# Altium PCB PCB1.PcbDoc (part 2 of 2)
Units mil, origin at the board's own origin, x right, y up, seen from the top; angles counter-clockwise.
Board outline 4950 x 3450 mil, 4 copper layers (Top Layer, VCC, GND, Bottom Layer), stack 79.834 mil thick; 154 components, 59 nets, 358 pads, 74 vias.
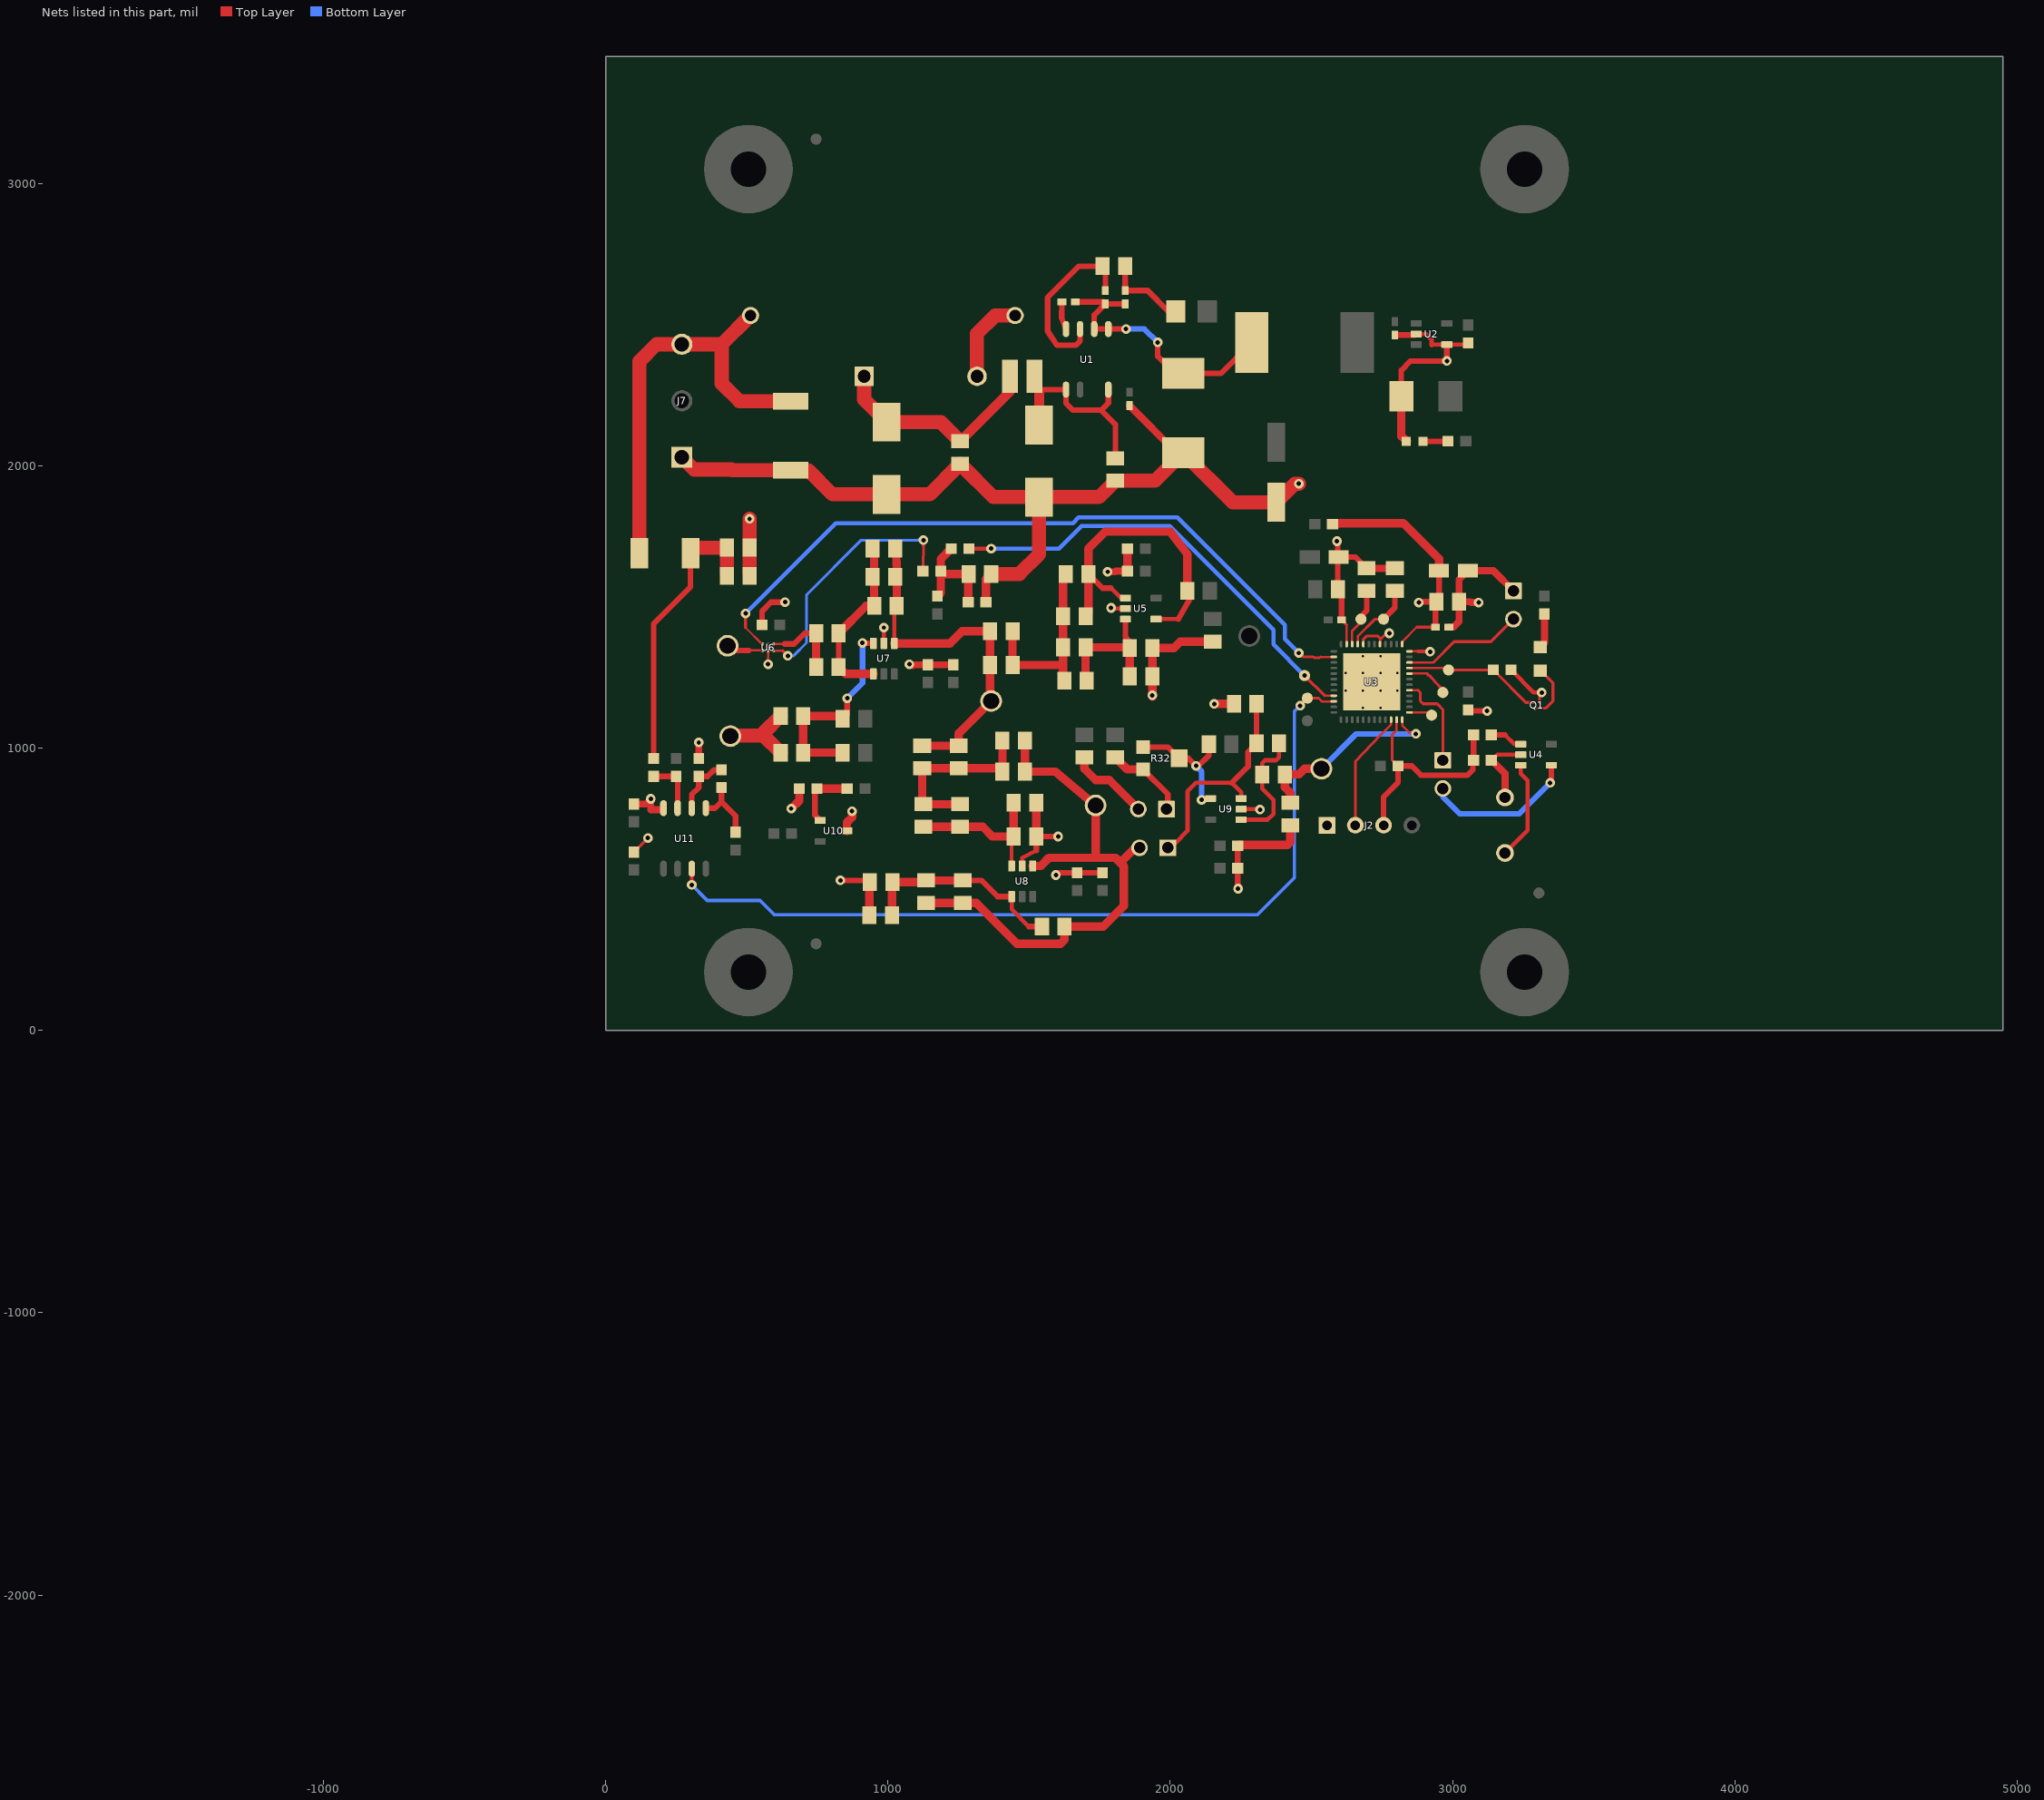
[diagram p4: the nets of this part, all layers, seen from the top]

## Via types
v1: diameter 34, hole 16, Top Layer to Bottom Layer, 62 vias
v2: diameter 19.68, hole 7.87, Top Layer to Bottom Layer, 12 vias

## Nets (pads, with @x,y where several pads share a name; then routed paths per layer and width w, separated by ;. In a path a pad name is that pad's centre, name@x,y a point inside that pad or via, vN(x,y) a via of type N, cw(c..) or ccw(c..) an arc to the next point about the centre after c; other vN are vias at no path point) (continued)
AGND: C2.2 C3.2 C5.2 C6.2 C7.2 C8.2 C9.2 C10.2 C11.2 C12.2 C13.2 C14.2 C15.2 C16.1 C17.1 C18.2 C19.2 C20.2 C21.2 C22.1 C23.1 C24.2 C25.2 C26.1 C31.2 C32.2 C37.2 C38.2 C39.2 C40.2 C41.2 C42.2 C43.2 C44.2 C45.2 D3.2 D4.1 D5.2 D6.2 J2.1 J3.1 J6.1 J7.1 Q1.A2 R4.1 R6.1 R10.1 R24.2 R25.2 R28.1 R29.1 R32.3 R36.1 R38.1 R40.1 R48.1 S1.1 U2.2 U2.4 U3.36 U3.41 U3.44 U3.47 U3.49 U4.2 U5.2 U6.2 U7.2 U8.2 U9.2 U10.3 U11.4 | length 9008.4
  Top Layer w8: 575.59,1316.56 U6.2@575.59,1344.75 ; U3.47@2624.7,1368.12 2624.7,1436.46 ; U3.44@2683.76,1368.12 2683.76,1384.73 ; U3.41@2742.81,1368.12 2742.81,1383.79 ; U3.36@2847.15,1342.53 2876.83,1342.53
  Top Layer w10: C44.2@100,631.5 v1(150,681.5) ; v1(575.59,1296.56) 575.59,1316.56 ; C10.2@2606.91,1454.26 2624.7,1436.46 ; 2683.76,1384.73 2695.59,1396.56 2735.59,1396.56 2745.59,1386.56 2765.59,1406.56 v1(2775.59,1406.56) ; Q1.A2@3308.53,1161.56 3308.53,1183.46 3315.59,1190.52 v1(3315.59,1196.56)
  Top Layer w12: 2877.15,1342.21 2911.55,1342.21 2912.52,1341.25 v1(2920.59,1341.25)
  Top Layer w15: U7.2@985.59,1370.7 985.59,1406.56 ; U8.2@1475.59,582.15 1475.59,610.95 1525.59,636.56 ; v1@1792.6,1493.94 U5.2@1841.46,1493.94 ; U9.2@2251.24,783.63 v1@2315.69,783.63 ; U2.2@2871.46,2466.56 2905.91,2466.56 2925.59,2446.88 2925.59,2426.56 2928.19,2429.16 U2.4@2979.72,2429.16 3049.68,2429.16 C6.2@3055.59,2435.07 ; C41.2@3139.05,956.56 3158.74,976.25 U4.2@3241.46,976.25 ; R6.1@3207.09,1276.56 3287.09,1196.56 v1(3315.59,1196.56)
  Top Layer w20: C26.1@554.09,1436.56 554.09,1485.07 585.59,1516.56 v1(635.59,1516.56) ; v1(831.63,530.97) 905.77,530.97 ; R24.2@928.52,518.04 934.39,523.9 R24.2@935.59,525.1 ; 1525.59,636.56 R28.1@1525.59,686.56 v1(1602.78,686.56) ; v1(1594.67,549.99) 1602.74,558.06 C37.2@1670,558.06 C39.2@1760,558.06 ; v1(1789.98,1496.56) v1@1792.6,1493.94 ; R32.3@1903.8,924.26 1991.18,836.88 1991.18,788.02 J6.1@1986.79,783.63 ; C38.2@2238.92,653.94 C40.2@2238.92,573.94 2238.92,503.1 v1(2240.08,501.94) ; v1@2315.69,783.63 v1(2317.76,781.56) ; v1(2590.59,1732.63) 2593.29,1729.94 C12.2@2593.29,1562.36 2606.91,1548.74 C10.2@2606.91,1454.26 ; C11.2@2596.77,1676.56 2655.59,1676.56 C17.1@2695.59,1636.56 ; C5.2@2795.59,2462.94 2867.83,2462.94 U2.2@2871.46,2466.56 ; D3.2@2818.27,2246.56 2818.27,2337.82 2851.14,2370.7 v1(2979.72,2370.7) U2.4@2979.72,2429.16 ; C21.2@3062.09,1131.56 v1(3122.17,1131.56)
  Top Layer w25: C44.2@100,631.5 C44.2@105.05,636.54 ; C45.2@100,801.5 141.5,801.5 v1(160,820) 160,781.5 199.21,781.5 U11.4@205,787.28 ; R10.1@330,962.8 v1(330,1020) ; v1@1087.36,1292.63 1089.86,1295.12 C31.2@1141.2,1295.12 C32.2@1231.2,1295.12 ; v1(1777.81,1624.18) 1804.63,1624.18 1807.01,1626.56 C24.2@1848.5,1626.56 ; R4.1@1855.59,2212.94 2022.46,2046.07 D6.2@2045.59,2046.07 ; C17.1@2695.59,1636.56 C16.1@2795.59,1636.56 ; C15.2@2986.91,1428.02 3003.29,1428.02 3023.29,1448.02 C13.2@3023.29,1518.02 ; v1(3092.17,1515.32) 3065.98,1515.32 3063.29,1518.02 C13.2@3023.29,1518.02 ; C41.2@3139.05,956.56 3185.59,910.03 S1.1@3185.59,824.99 ; J3.1@3215.59,1556.56 3144.13,1628.02 C14.2@3054.47,1628.02 3023.29,1596.84 C13.2@3023.29,1518.02
  Top Layer w30: v1(657.56,785.43) 685.75,813.61 R38.1@685.75,856.56 ; U10.3@854.49,706.56 854.49,736.64 872.81,754.97 v1(872.81,776.18) ; R25.2@934.39,408.04 R24.2@934.39,523.9 ; R40.1@1347.09,1516.56 1347.09,1598.06 C20.2@1365.59,1616.56 ; R28.1@1525.59,686.56 R29.1@1525.59,806.56 ; C42.2@1805.59,966.56 1847.89,924.26 R32.3@1903.8,924.26 ; C24.2@1848.5,1626.56 C25.2@1848.5,1706.56 ; v1@1936.69,1182.37 C23.1@1936.69,1253.94 C22.1@1936.69,1353.94 2012.97,1353.94 2035.59,1376.56 C18.2@2150,1376.56 ; v1(2155.59,1156.56) R36.1@2225.59,1156.56 ; C38.2@2238.92,653.94 2241.54,656.56 2415.59,656.56 2425.59,666.56 C19.2@2425.59,726.56 ; 2818.27,2104.04 D3.2@2818.27,2246.56 ; 2820.26,2104.04 D5.2@2837.74,2086.56
  Top Layer w50: J7.1@270,2030 313.44,1986.56 445.59,1986.56 447.83,1984.32 D4.1@655.59,1984.32 717.83,1984.32 803.54,1898.61 C7.2@995.59,1898.61 1147.64,1898.61 C8.2@1255.59,2006.56 1373.54,1888.61 C2.2@1535.59,1888.61 ; C43.2@510,1620 510,1720 v1(510,1811.57) ; C20.2@1365.59,1616.56 1465.59,1616.56 1535.59,1686.56 C2.2@1535.59,1888.61 ; v1(2455.59,1936.56) 2441.89,1936.56 C9.2@2375.59,1870.26 2221.4,1870.26 D6.2@2045.59,2046.07 1946.08,1946.56 C3.2@1805.59,1946.56 1747.64,1888.61 C2.2@1535.59,1888.61
  other v1: 1936.69,1186.56 1075.59,1296.56 985.59,1426.56
  other v2: 2681.65,1142.72 2744.92,1142.72 2621.75,1202.62 2681.65,1202.62 2744.92,1202.62 2804.82,1202.62 2621.75,1265.89 2681.65,1265.89 2744.92,1265.89 2804.82,1265.89 2681.65,1325.79 2744.92,1325.79
COMP_OP: C19.1 R42.2 TP9.1 U3.24 | length 713.4
  Top Layer w8: U3.24@2821.55,1100.4 2821.55,1080 2829.05,1072.5 2844.05,1057.5 2851.55,1050 v1(2870,1050)
  Top Layer w30: C19.1@2425.59,806.56 2425.59,840.56 2405.59,860.56 R42.2@2405.59,906.56 2455.59,906.56 2475.59,926.56 TP9.1@2535.59,926.56
  Bottom Layer w20: TP9.1@2535.59,926.56 2655.59,1046.56 2659.03,1050 v1(2870,1050)
DVCC: C13.1 C14.1 C15.1 L3.1 U3.37 | length 890.2
  Top Layer w8: U3.37@2821.55,1368.12 2821.55,1376.29 2873.29,1428.02
  Top Layer w10: 2873.29,1428.02 C15.1@2939.67,1428.02
  Top Layer w20: v1(2880.59,1515.32) 2885.2,1515.32 2887.89,1518.02 C13.1@2943.29,1518.02 ; C15.1@2939.67,1428.02 2939.67,1514.4 C13.1@2943.29,1518.02 ; C14.1@2952.11,1628.02 2952.11,1526.84 C13.1@2943.29,1518.02
  Top Layer w30: L3.1@2574.78,1792.36 2591.39,1792.36 2595.59,1796.56 2825.59,1796.56 2952.11,1670.05 C14.1@2952.11,1628.02
FAULT: J3.2 U3.34 | length 432
  Top Layer w8: U3.34@2847.15,1303.16 2932.18,1303.16
  Top Layer w10: 2932.18,1303.16 3005.59,1376.56 3135.59,1376.56 J3.2@3215.59,1456.56
NetC1_1: C1.1 U1.4 | length 98.7
  Top Layer w20: C1.1@1616.42,2580.03 1615.59,2522.55 U1.4@1630.59,2484.16
NetC1_2: C1.2 C4.2 D6.1 L2.1 R2.1 U1.1 U1.2 | length 981.9
  Top Layer w20: C1.2@1663.66,2580.03 1762.95,2580.03 R2.1@1770.04,2572.94 ; C4.2@1840.04,2572.94 R2.1@1770.04,2572.94 ; v1(1843.19,2484.16) U1.1@1780.59,2484.16 U1.2@1730.59,2484.16 1730.59,2533.49 R2.1@1770.04,2572.94 ; v1(1955.59,2436.56) 1955.59,2387.05 2015.59,2327.05 D6.1@2045.59,2327.05 2179.07,2327.05 L2.1@2288.58,2436.56
  Bottom Layer w20: v1(1843.19,2484.16) 1907.99,2484.16 v1(1955.59,2436.56)
NetC2_1: C2.1 C3.1 L1.2 U1.5 U1.8 | length 701.2
  Top Layer w20: L1.2@1518.9,2283.25 1532.56,2269.59 U1.5@1630.59,2269.59 1630.59,2221.56 1655.59,2196.56 1755.59,2196.56 ; U1.8@1780.59,2269.59 1780.59,2221.56 1755.59,2196.56 ; C3.1@1805.59,2026.56 1805.59,2146.56 1755.59,2196.56
  Top Layer w35: L1.2@1532.56,2269.59 1535.59,2266.56 C2.1@1535.59,2144.51
NetC4_1: C4.1 D2.1 R1.2 | length 296.3
  Top Layer w20: R1.2@1840.04,2706.56 C4.1@1840.04,2620.18 1919.88,2620.18 1993.5,2546.56 D2.1@2019.49,2546.56
NetC7_1: C7.1 C8.1 D1.1 L1.1 | length 786.5
  Top Layer w35: C8.1@1255.59,2086.56 1432.28,2263.25 L1.1@1432.28,2316.56
  Top Layer w50: D1.1@915.59,2316.56 915.59,2234.51 C7.1@995.59,2154.51 1187.64,2154.51 C8.1@1255.59,2086.56
NetC16_2: C16.2 TP14.1 U3.45 | length 260.5
  Top Layer w8: U3.45@2664.07,1368.12 2664.07,1395.05
  Top Layer w10: 2664.07,1395.05 2725.59,1456.56 TP14.1@2755.59,1456.56
  Top Layer w20: TP14.1@2755.59,1456.56 2795.59,1496.56 C16.2@2795.59,1556.56
NetC17_2: C17.2 TP15.1 U3.46 | length 209.7
  Top Layer w8: U3.46@2644.39,1368.12 2644.39,1415.36
  Top Layer w10: 2644.39,1415.36 2675.59,1446.56 TP15.1@2675.59,1456.56
  Top Layer w20: TP15.1@2675.59,1456.56 2675.59,1466.56 2695.59,1486.56 C17.2@2695.59,1556.56
NetC20_1: C20.1 R8.2 R9.1 R39.2 R40.2 | length 391.9
  Top Layer w30: R39.2@1175.59,1538.06 1187.09,1549.55 R9.1@1187.09,1626.56 ; R8.2@1224.09,1706.56 1187.09,1669.55 R9.1@1187.09,1626.56 ; R40.2@1284.09,1516.56 1284.09,1615.07 C20.1@1285.59,1616.56 1197.09,1616.56 R9.1@1187.09,1626.56
NetC22_2: C22.2 C23.2 R13.2 R16.2 U5.3 | length 485.9
  Top Layer w20: R16.2@1700,1243.57 R16.2@1704.39,1239.18 ; U5.3@1841.46,1456.54 1841.46,1392.18 1856.69,1376.94 C22.2@1856.69,1353.94 C22.2@1854.07,1356.56
  Top Layer w30: R16.2@1700,1243.57 R13.2@1700,1356.56 C22.2@1854.07,1356.56 ; C23.2@1856.69,1253.94 C22.2@1856.69,1353.94
NetC27_1: C27.1 R14.1 R17.1 R18.2 R19.2 U7.4 | length 621.3
  Top Layer w20: R19.2@825.59,1286.56 R18.2@825.59,1406.56
  Top Layer w30: R19.2@825.59,1286.56 849.72,1262.43 U7.4@948.19,1262.43 ; R18.2@825.59,1406.56 922.66,1503.63 C27.1@951.2,1503.63 951.2,1623.63 R14.1@951.14,1706.56
NetC27_2: C27.2 C33.2 C36.2 R12.1 R14.2 R15.1 R17.2 TP6.1 U7.1 | length 1260.7
  Top Layer w15: U7.1@1022.99,1370.7 C27.2@1022.99,1495.42
  Top Layer w20: C27.2@1022.99,1495.42 C27.2@1031.2,1503.63
  Top Layer w30: U7.1@1022.99,1370.7 1219.72,1370.7 1262.66,1413.63 R12.1@1361.2,1413.63 R15.1@1361.2,1313.31 ; R14.2@1028.88,1706.56 1031.2,1623.63 C27.2@1031.2,1503.63 ; C33.2@1121.2,1008.02 C36.2@1251.2,1008.02 1251.2,1052.17 TP6.1@1365.59,1166.56 1361.2,1170.95 R15.1@1361.2,1293.94
NetC28_1: C28.1 C29.1 R41.1 U5.1 U5.4 | length 1151.5
  Top Layer w15: 1790,1566.56 1825.22,1531.34 U5.1@1841.46,1531.34 ; U5.4@1949.72,1456.54 2028.69,1456.54
  Top Layer w20: C28.1@1700,1466.56 C28.1@1710,1476.56 ; C29.1@1710,1616.56 1760,1566.56 1790,1566.56 ; 2028.69,1456.54 2069.98,1529.76 R41.1@2069.98,1558.37
  Top Layer w30: C28.1@1710,1476.56 C29.1@1710,1616.56 ; C29.1@1710,1616.56 1709.98,1706.54 1770,1766.56 2000,1766.56 2059.98,1686.59 2059.98,1646.56 2059.98,1566.56 R41.1@2049.98,1556.56
NetC28_2: C28.2 C29.2 R12.2 R13.1 R15.2 R16.1 | length 684.4
  Top Layer w20: R16.1@1620,1243.57 R16.1@1624.39,1239.18 ; C29.2@1620,1606.56 C29.2@1630,1616.56
  Top Layer w30: R12.2@1441.2,1413.63 R15.2@1441.2,1293.94 1613.88,1293.94 1620,1300.07 ; R16.1@1620,1243.57 1620,1300.07 ; C29.2@1620,1606.56 C28.2@1620,1466.56 R13.1@1620,1356.56 1620,1300.07
NetC30_1: C30.1 R24.1 R25.1 R26.1 R27.1 U8.4 | length 744.2
  Top Layer w15: U8.4@1438.19,473.88 1438.19,428.35 1498.52,368.02
  Top Layer w20: R24.1@1014.39,523.9 R24.1@1015.59,525.1 ; R26.1@1129.7,525.1 R26.1@1135.59,530.99 ; R27.1@1265.59,530.99 1331.16,530.99 1388.27,473.88 U8.4@1438.19,473.88 ; 1498.52,368.02 C30.1@1545.59,368.02
  Top Layer w30: R25.1@1014.39,408.04 R24.1@1014.39,523.9 ; R24.1@1015.59,525.1 R26.1@1129.7,525.1 ; R26.1@1135.59,530.99 R27.1@1265.59,530.99
NetC30_2: C30.2 J5.2 R26.2 R27.2 R31.2 R35.2 TP8.1 U8.1 | length 2009.6
  Top Layer w30: R26.2@1135.59,450.99 R27.2@1265.59,450.99 1312.93,450.99 1457.36,306.56 1611.2,306.56 1625.59,320.95 C30.2@1625.59,368.02 1762.66,368.02 1835.59,440.95 1835.59,580.95 1822.79,593.76 ; R31.2@1485.59,1026.56 R35.2@1485.59,916.56 1592.66,916.56 TP8.1@1735.59,796.56 1735.59,610.95 ; U8.1@1512.99,582.15 1541.18,582.15 1569.98,610.95 1735.59,610.95 ; J5.2@1891.18,646.56 1875.59,646.56 1822.79,593.76 ; 1735.59,610.95 1805.59,610.95 1822.79,593.76
NetC33_1: C33.1 C34.2 C35.2 C36.1 R31.1 R35.1 | length 658
  Top Layer w30: C35.2@1255.59,800.95 C34.2@1125.59,800.95 1121.2,805.34 C33.1@1121.2,928.02 C36.1@1251.2,928.02 1394.13,928.02 R35.1@1405.59,916.56 R31.1@1405.59,1026.56
NetC34_1: C34.1 C35.1 R28.2 R29.2 U8.3 | length 561.7
  Top Layer w12: U8.3@1438.19,582.15 R28.2@1438.19,679.16
  Top Layer w20: R28.2@1438.19,679.16 R28.2@1445.59,686.56
  Top Layer w30: C34.1@1125.59,720.95 C35.1@1255.59,720.95 1335.59,720.95 1369.98,686.56 R28.2@1445.59,686.56 R29.2@1445.59,806.56
NetC43_1: C43.1 R45.1 R46.1 R48.2 | length 970.7
  Top Layer w20: R46.1@170,962.8 170,1440 300.55,1570.55 R45.1@300.55,1690
  Top Layer w50: R45.1@330,1710 429.45,1710 C43.1@430,1620
NetD1_2: D1.2 RF1.1 | length 312.8
  Top Layer w50: D1.2@1315.59,2316.56 1315.59,2468.06 1379.71,2532.18 RF1.1@1450.37,2532.18
NetD5_1: D5.1 R3.1 | length 89
  Top Layer w20: D5.1@2894.8,2086.56 R3.1@2983.78,2086.56
NetD8_1: D8.1 Q1.B1 Q1.B2 | length 203.5
  Top Layer w10: Q1.B1@3288.85,1141.88 Q1.B2@3308.53,1141.88 3330.91,1141.88 3355.59,1166.56 3355.59,1229.99 D8.1@3310.99,1274.59
NetD8_2: D8.2 R5.2 | length 123.8
  Top Layer w25: D8.2@3310.99,1357.26 3325.59,1371.86 R5.2@3325.59,1475.07
NetJ4_2: J4.2 U4.4 | length 514.4
  Top Layer w20: v1(3345.59,876.56) 3349.72,880.7 U4.4@3349.72,938.84
  Bottom Layer w20: 2965.59,826.56 3025.59,766.56 3235.59,766.56 v1(3345.59,876.56)
NetJ5_1: J5.1 R34.1 R36.2 U9.3 | length 786.9
  Top Layer w15: J5.1@1986.79,663.63 2018.25,663.63 2061.18,706.56 2061.18,846.56 2091.18,876.56 2217.67,876.56 2251.24,842.99 U9.3@2251.24,821.03
  Top Layer w20: 2217.67,876.56 2275.59,934.48 2275.59,986.56 R34.1@2305.59,1016.56 R36.2@2305.59,1156.56
NetJ6_2: J6.2 R43.2 | length 290.4
  Top Layer w30: R43.2@1695.59,966.56 1695.59,926.56 1735.59,886.56 1783.86,886.56 J6.2@1886.79,783.63
NetQ1_A1: Q1.A1 R6.2 TP3.1 U3.33 | length 492.2
  Top Layer w8: U3.33@2847.15,1283.47 TP3.1@2978.68,1283.47
  Top Layer w10: TP3.1@2978.68,1283.47 TP3.1@2985.59,1276.56 R6.2@3144.09,1276.56 3259.09,1161.56 Q1.A1@3288.85,1161.56
NetR1_1: R1.1 R2.2 U1.3 | length 640.5
  Top Layer w20: U1.3@1680.59,2484.16 1680.59,2441.56 1665.59,2426.56 1598.92,2426.56 1565.59,2476.56 1565.59,2595.58 1676.57,2706.56 R1.1@1760.04,2706.56 1770.04,2696.56 R2.2@1770.04,2620.18
NetR10_2: R10.2 R44.1 U11.2 | length 212.4
  Top Layer w20: U11.2@305,787.28 305,835 330,860 R10.2@330,899.8 361.26,899.8 384.25,922.8 R44.1@410,922.8
NetR11_1: R11.1 U4.1 | length 118
  Top Layer w15: 3185.59,1046.56 3218.5,1013.65 U4.1@3241.46,1013.65
  Top Layer w20: R11.1@3137.09,1046.56 3185.59,1046.56
NetR18_1: R18.1 R19.1 U6.4 | length 286.1
  Top Layer w8: U6.4@595.28,1368.37 633.78,1368.37
  Top Layer w20: 633.78,1368.37 667.4,1368.37 705.59,1406.56 R18.1@745.59,1406.56
  Top Layer w30: R19.1@745.59,1286.56 R18.1@745.59,1406.56
NetR20_1: R20.1 R21.1 TP7.1 | length 295.3
  Top Layer w50: TP7.1@445.59,1046.56 448.52,1043.63 560,1043.63 ; R21.1@620,983.63 560,1043.63 ; R20.1@620,1113.63 560,1053.63 560,1043.63
NetR20_2: R20.2 R21.2 R22.1 R23.1 U7.3 | length 752
  Top Layer w20: R22.1@830,1113.63 R22.1@840,1103.63 845.59,1109.22 855.59,1119.22 v1(855.59,1176.56) ; v1(909.72,1372.43) 909.72,1370.7 U7.3@948.19,1370.7
  Top Layer w30: R22.1@830,1113.63 R20.2@700,1113.63 R21.2@700,983.63 R23.1@840,983.63
  Bottom Layer w20: v1(855.59,1176.56) 909.72,1230.7 v1(909.72,1372.43)
NetR30_1: R30.1 R32.1 R32.2 U9.4 | length 477.8
  Top Layer w20: R32.1@1903.8,1003 1992.38,1003 R32.2@2031.75,963.63 2064.11,963.63 v1(2091.18,936.56) 2099.73,936.56 2136.79,973.63 R30.1@2136.79,1013.63 ; v1(2111.18,816.56) 2115.65,821.03 U9.4@2142.97,821.03
  Bottom Layer w20: v1(2091.18,936.56) 2111.18,916.56 v1(2111.18,816.56)
NetR34_2: R34.2 R42.1 U9.1 | length 437.6
  Top Layer w15: U9.1@2251.24,746.23 2345.26,746.23 2365.59,766.56 2365.59,816.56 2325.59,856.56 R42.1@2325.59,906.56 2325.59,946.56 2335.59,956.56 2375.59,956.56 2385.59,966.56 R34.2@2385.59,1016.56
NetR37_1: R37.1 R38.2 U10.1 | length 230.2
  Top Layer w20: R38.2@748.74,856.56 741.63,849.45 741.63,762.33 U10.1@760,743.96
  Top Layer w30: R38.2@748.74,856.56 R37.1@855.75,856.56
NetR44_2: R44.2 R47.1 U11.1 | length 243.4
  Top Layer w20: U11.1@355,787.28 387.28,787.28 410,810 ; R44.2@410,859.8 410,810 ; R47.1@460,701.5 460,760 410,810
NetR46_2: R46.2 R49.2 U11.3 | length 194.6
  Top Layer w20: R46.2@170,899.8 R49.2@250,899.8 255,894.8 U11.3@255,787.28
NetS1_2: S1.2 U4.3 | length 353.8
  Top Layer w15: S1.2@3185.59,628.14 3265.59,708.14 3265.59,885.38 3241.46,909.51 U4.3@3241.46,938.84
NetTP5_1: TP5.1 U6.1 | length 122.1
  Top Layer w8: 506.42,1345.73 U6.1@555.91,1345.73
  Top Layer w20: TP5.1@441.2,1363.63 459.09,1345.73 506.42,1345.73
NetTP10_1: TP10.1 U3.25 | length 82.4
  Top Layer w8: U3.25@2847.15,1125.99 2916.16,1125.99 TP10.1@2925.59,1116.56
NetTP13_1: TP13.1 U3.32 | length 153.5
  Top Layer w8: U3.32@2847.15,1263.79 2908.37,1263.79
  Top Layer w10: 2908.37,1263.79 2915.72,1256.44 2917.96,1256.44 2935.46,1238.94 2935.46,1236.69 2965.59,1206.56 TP13.1@2965.59,1196.56
PWM_TEST: R8.1 TP17.1 U3.9 | length 1605.1
  Top Layer w8: 2547.11,1185.05 U3.9@2579.43,1185.05
  Top Layer w10: v1(2475.59,1256.56) 2547.11,1185.05
  Top Layer w15: R8.1@1287.09,1706.56 v1(1365.59,1706.56)
  Bottom Layer w15: v1(1365.59,1706.56) 1605.59,1706.56 1685.59,1786.56 1997.52,1786.56 2365.59,1418.49 2365.59,1366.56 v1(2475.59,1256.56)
RESET: C41.1 J2.3 R7.1 R11.2 U3.23 | length 821.6
  Top Layer w8: 2801.87,1062.84 U3.23@2801.87,1100.4
  Top Layer w10: 2801.87,1062.84 2785.59,1046.56 2785.59,958.06 R7.1@2807.09,936.56
  Top Layer w20: J2.3@2755.59,726.56 2755.59,826.56 2807.09,878.06 R7.1@2807.09,936.56 2855.59,936.56 2888.19,903.96 3052.99,903.96 3072.13,923.1 3072.13,956.56 3074.09,958.53 R11.2@3074.09,1046.56
TEST: R9.2 U6.3 | length 959
  Top Layer w8: U6.3@595.28,1344.75 627.4,1344.75
  Top Layer w10: 627.4,1344.75 v1(645.59,1326.56) ; R9.2@1124.09,1626.56 v1(1125.59,1736.56) 1125.59,1716.56 1124.09,1715.07
  Bottom Layer w10: v1(645.59,1326.56) 665.59,1326.56 711.59,1372.56 711.59,1542.56 905.22,1736.19 v1(1125.59,1736.56) 1106.34,1736.56 1105.96,1736.19
TEST/SBWTCK: J2.2 U3.22 | length 424.9
  Top Layer w8: 2745.59,1046.56 2782.18,1083.16 U3.22@2782.18,1100.4
  Top Layer w10: J2.2@2655.59,726.56 2655.59,951.76 2745.59,1046.56
TEST_EN: U3.2 U6.6 | length 2595.5
  Top Layer w8: 495.59,1426.56 553.78,1368.37 U6.6@555.91,1368.37 ; 2532.29,1322.84 U3.2@2579.43,1322.84
  Top Layer w10: v1(2455.59,1336.56) 2469.31,1322.84 2506.96,1322.84 2510.15,1319.65 2529.1,1319.65 2532.29,1322.84
  Top Layer w12: 495.59,1426.56 v1(495.59,1476.56)
  Bottom Layer w15: v1(495.59,1476.56) 815.59,1796.56 1655.59,1796.56 1675.59,1816.56 2025.59,1816.56 2405.59,1436.56 2405.59,1386.56 v1(2455.59,1336.56)
VAC_IN: D4.2 J7.3 R45.2 RF1.2 | length 1550
  Top Layer w50: R45.2@119.45,1690 119.45,2369.45 180,2430 J7.3@270,2430 411.18,2430 ; RF1.2@513.36,2532.18 411.18,2430 ; D4.2@655.59,2228.81 473.35,2228.81 411.18,2290.97 411.18,2430
VIN_ZC: TP11.1 U3.10 U11.7 | length 3030.5
  Top Layer w8: 2536.79,1165.36 U3.10@2579.43,1165.36
  Top Layer w10: TP11.1@2485.59,1176.56 2525.59,1176.56 2536.79,1165.36
  Top Layer w12: v1(305,515) 305,545 U11.7@310,550 ; v1(2460,1150) 2460,1150.97 TP11.1@2485.59,1176.56
  Bottom Layer w12: v1@300,520 360,460 546.76,460 596.88,409.87 2309.87,409.87 2440,540 2440,1130 v1(2460,1150)
WDI: J4.1 U3.29 | length 344.3
  Top Layer w8: U3.29@2847.15,1204.73 2877.42,1204.73
  Top Layer w10: 2877.42,1204.73 2885.59,1196.56 2885.59,1166.56 2895.59,1156.56 2945.59,1156.56 2965.59,1136.56 J4.1@2965.59,956.56
pads on no net: FID1.1 FID2.1 FID3.1 H1.1 H2.1 H3.1 H4.1 J7.2 U1.6 U3.4 U3.5 U3.6 U3.7 U3.8 U3.12 U3.13 U3.14 U3.15 U3.16 U3.17 U3.18 U3.19 U3.20 U3.21 U3.26 U3.27 U3.28 U3.30 U3.31 U3.35 U3.38 U3.39 U3.40 U3.42 U3.43

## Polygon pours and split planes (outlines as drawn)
AGND on GND "GND-No Net" (solid, pour order 18): 375.59,347.37 90,347.37 90,2046.56 375.59,2046.56 765.59,2046.56 855.59,1956.56 1675.59,1956.56 2205.59,1956.56 2425.59,1956.56 2495.59,1956.56 2605.59,2066.56 2723.62,2184.59 2723.62,2188.53 2723.62,2704.59 2725.59,2706.56 2725.59,2816.56 3445.59,2816.56 3455.59,2806.56 3455.59,346.56 376.73,346.56 376.16,347.13
+3.3V on VCC "VCC-No Net" (solid, pour order 20): 505.59,426.56 3415.59,426.56 3415.59,1866.56 3165.59,2116.56 3155.59,2116.56 3155.59,2606.56 2795.59,2606.56 2795.59,2186.56 2345.59,1736.56 2375.59,1766.56 515.59,1766.56 505.59,1756.56 140,1766.56 140,426.56

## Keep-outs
Keep-Out Layer:
  lines w7: -1240,-2530 -1240,-530 ; -1240,-2530 760,-2530 ; -1240,-2530 -1240,-530 ; -1240,-2530 760,-2530 ; -1240,-530 760,-530 ; -1240,-530 760,-530 ; 760,-2530 760,-530 ; 760,-2530 760,-530
  lines w10: 0,0 3520,0 ; -1875,-1675 -1875,1675 -1875,-1675
  text ".Layer_Name" at 577,-858.49 h60

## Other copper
Top Layer:
  text ".Layer_Name" at 577,-858.49 h60
Bottom Layer:
  text ".Layer_Name" at 577,-858.49 h60

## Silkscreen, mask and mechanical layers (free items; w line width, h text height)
Top Overlay:
  region: 2345.59,316.56 2045.59,316.56 2045.59,216.56 2345.59,216.56
  lines w10: 40,1780 40,2840 50,2870 2650,2870 2760,2760 2760,2120 2410,1770 1820,1770 640,1770 50,1770 40,1780
  text "HV: Do not touch" at 1150,2810 h40
  text "85-265Vac" at 120,2710 h60
  text "TP1" at 210,2560 h60
  text "3.3V" at 2745.59,1966.56 h60
  text "TP2" at 220,1800 h60
  text "155mV" at 70,1190 h60
  text "FAULT" at 3435.59,1146.56 h60 r90
  text "TIDA-00929-E1" at 1745.59,106.56 h108.27
  text ".Layer_Name" at 577,-858.49 h60
Bottom Overlay:
  text ".Layer_Name" at 577,-858.49 h60
Top Paste:
  text ".Layer_Name" at 577,-858.49 h60
Bottom Paste:
  text ".Layer_Name" at 577,-858.49 h60
Top Solder:
  text ".Layer_Name" at 577,-858.49 h60
  text ".Layer_Name" at 577,-858.49 h60
Bottom Solder:
  text ".Layer_Name" at 577,-858.49 h60
Drill Guide:
  text ".Layer_Name" at 577,-858.49 h60
M1 Board Outline:
  lines w10: 0,0 3520,0 3520,3400 0,3400 0,0
  text ".Layer_Name" at 577,-858.49 h60
M2 Board Dimensions:
  rectangle: 125,-400 500,-275
  rectangle: 0,-275 125,-150
  lines w7: 0,-275 1000,-275 ; 125,-400 125,-150 ; 250,-400 250,-150 ; 500,-400 500,-150 ; 750,-400 750,-150 ; 0,-400 0,-150 1000,-150 1000,-400 0,-400
  text ".Layer_Name" at 577,-858.49 h60
M3 3D STEP Top:
  text ".Layer_Name" at 577,-858.49 h60
M4 3D STEP Bottom:
  text ".Layer_Name" at 577,-858.49 h60
M5 Assembly Top:
  lines w10: -292,-930.17 6308,-930.17 ; -292,-726.83 6310,-726.83 ; -292,-523.5 -292,-1133.5 3713,-1133.5 6310,-1133.5 6310,-523.5 -291.5,-523.5 -291.5,-1133.5 1284,-1133.5 ; 2173,-1133.5 2173,-523.5 ; 3440,-726.83 3440,-523.5 ; 4280,-726.83 4280,-523.5 ; 4902,-1140 4902,-937.17
  text "COMPONENTS MARKED 'DNP' SHOULD NOT BE POPULATED." at 1153.5,-318.5 h60
  text "ASSEMBLY VARIANT:" at 1153,-434 h60
  text ".VariantName" at 2189,-434 h60
  text "PCB VIEWED FROM TOP SIDE" at -228.5,-655.67 h60
  text "BOARD #:" at 2248,-655.67 h60
  text ".PRJ_Number" at 2793.5,-655.67 h60
  text "REV:" at 3638,-655.67 h60
  text ".PCB_Rev" at 3929.5,-655.67 h60
  text "SVN REV:" at 4476,-655.67 h60
  text ".VersionControl_RevNumber" at 4982,-655.67 h60
  text "TID #:" at 2248,-859 h60
  text ".TID" at 2793.5,-859 h60
  text "PLOT NAME =" at -228.5,-1064.34 h60
  text ".plot_File_Name" at 577,-1064.34 h60
  text "GENERATED    :" at 2250,-1064.34 h60
  text ".Print_Date" at 3119.5,-1064.34 h60
  text ".Print_Time" at 3848.5,-1064.34 h60
  text "TEXAS INSTRUMENTS" at 5113,-1064.34 h60
M6 Assembly Bottom:
  lines w10: -292.5,-727.33 6309.5,-727.33 ; -290.5,-930.67 6309.5,-930.67 ; 1115.5,-1140.5 1115.5,-937.67 ; 1737.5,-727.33 1737.5,-524 ; 2577.5,-727.33 2577.5,-524 ; 3844.5,-1134 3844.5,-524 ; 4733.5,-1134 6309,-1134 6309,-524 -292.5,-524 -292.5,-1134 2304.5,-1134 6309.5,-1134 6309.5,-524
  text "COMPONENTS MARKED 'DNP' SHOULD NOT BE POPULATED." at 6102,-318 h60
  text ".VariantName" at 5058,-434 h60
  text "ASSEMBLY VARIANT:" at 6097,-434 h60
  text ".VersionControl_RevNumber" at 1035.5,-656.17 h60
  text "SVN REV:" at 1541.5,-656.17 h60
  text ".PCB_Rev" at 2088,-656.17 h60
  text "REV:" at 2379.5,-656.17 h60
  text ".PRJ_Number" at 3224,-656.17 h60
  text "BOARD #:" at 3769.5,-656.17 h60
  text "PCB VIEWED FROM BOTTOM SIDE" at 6246,-656.17 h60
  text ".TID" at 3224,-859.5 h60
  text "TID #:" at 3769.5,-859.5 h60
  text "TEXAS INSTRUMENTS" at 904.5,-1064.84 h60
  text ".Print_Time" at 2169,-1064.84 h60
  text ".Print_Date" at 2898,-1064.84 h60
  text "GENERATED    :" at 3767.5,-1064.84 h60
  text ".plot_File_Name" at 5440.5,-1064.84 h60
  text "PLOT NAME =" at 6246,-1064.84 h60
M9 Title Sheet:
  drawing of 57 lines, arcs and shapes, not listed
  text "1" at 739.84,8036.5 h70
  text "2" at 3235.5,8036.5 h70
  text "3" at 5724.84,8036.5 h70
  text "4" at 8231.51,8036.5 h70
  text "5" at 10730.5,8036.5 h70
  text "6" at 13235.5,8036.5 h70
  text "A" at -416.5,6893.5 h70
  text "A" at 14383.5,6893.5 h70
  text "B" at -416.5,4513.5 h70
  text "B" at 14383.5,4513.5 h70
  text "C" at -416.5,2138.5 h70
  text "C" at 14383.5,2138.5 h70
  text "PROJECT TITLE:" at 11343.5,277.5 h45
  text ".PRJ_Title" at 11393.5,144.17 h70
  text "DESIGNED FOR:" at 11343.5,-23.5 h45
  text ".PRJ_Customer" at 11393.5,-163.5 h70
  text "D" at -416.5,-231.5 h70
  text "D" at 14383.5,-231.5 h70
  text "FILE NAME:" at 11343.5,-323.5 h45
  text ".PCB_File_Name_No_Path" at 11393.5,-443.5 h70
  text "Texas Instruments (TI) and/or its licensors do not warrant the accuracy or completeness of this specification" at 6374,-605.34 h45
  text "ENGINEER:" at 11343.5,-613.5 h45
  text "LAYOUT BY:" at 12848.5,-613.5 h45
  text "or any information contained therein. TI and/or its licensors do not warrant that this design will meet" at 6329.01,-718 h45
  text ".PRJ_Engineer" at 11393.5,-768.49 h70
  text ".PCB_Layout" at 12899,-768.49 h70
  text "the specifications, will be suitable for your application or fit for any particular purpose, or will operate in" at 6329.01,-830.67 h45
  text ".Layer_Name" at 577,-858.49 h60
  text "ALTIUM DESIGNER VERSION:" at 12848.5,-923.5 h45
  text "an implementation. TI and/or its licensors do not warrant that the design is production worthy. You should" at 6329.01,-943.33 h45
  text "completely validate and test your design implementation to confirm the system functionality for your application." at 6374,-1056 h45
  text ".print_Scale" at 11393.5,-1056.83 h70
  text ".Application_BuildNumber" at 12899,-1056.83 h70
  text "1" at 739.84,-1263.5 h70
  text "2" at 3235.5,-1263.5 h70
  text "3" at 5724.84,-1263.5 h70
  text "4" at 8231.51,-1263.5 h70
  text "5" at 10730.5,-1263.5 h70
  text "6" at 13235.5,-1263.5 h70
M10 Fab Notes:
  drawing of 173 lines, arcs and shapes, not listed
  text "DESIGN INFORMATION" at 12378.02,6201 h60
  text "MIN. TRACK WIDTH:" at 11733.46,6021 h60
  text "8" at 12829.7,6021 h60
  text "MIL" at 12984.46,6021 h60
  text "MIN. CLEARANCE:" at 11733.46,5889 h60
  text "0.2" at 12769.7,5889 h60
  text "mm" at 12984.46,5889 h60
  text "MIN. VIA PAD SIZE:" at 11733.46,5757 h60
  text "24" at 12799.71,5757 h60
  text "MIL" at 12984.46,5757 h60
  text "0.05mm (2MIL)" at 12428.46,5615.29 h60
  text "MINIMUM ANNULAR RING" at 11404.23,5611 h60
  text "EXTERNAL" at 13136.46,5611 h60
  text "PER" at 11604.23,5493 h60
  text "IPC-D-275 CLASS 2 LEVEL C" at 11824.23,5493 h60
  text "MIL, HOLES" at 13312.46,5380.71 h60
  text "+/-" at 12920,5380 h60
  text "+/-" at 13774,5380 h60
  text "REGISTRATION TOLERANCES:" at 11404.23,5375 h60
  text "METAL" at 12604,5375 h60
  text "5" at 13180.2,5375 h60
  text "3" at 14013.2,5375 h60
  text "MIL" at 14129.46,5375 h60
  text "+/-" at 13774,5262 h60
  text "HOLE SIZE TOLERANCE (UNLESS OTHERWISE SPECIFIED):" at 11404.23,5257 h60
  text "3" at 14013.2,5257 h60
  text "MIL" at 14129.46,5257 h60
  text "MATERIAL:" at 11329.46,5047.54 h60
  text "FR-4 High Tg" at 12315.9,4907.21 h60
  text "FR-408" at 11750.46,4898.64 h60
  text "OTHER" at 13238.46,4898.64 h60
  text "X" at 12161,4895 h60
  text "62 MIL (1.6mm) +/-10%" at 12070.56,4735.92 h60
  text "THICKNESS:" at 11404.23,4731.64 h60
  text "X" at 11942.4,4731.64 h60
  text "OTHER" at 13355.46,4731.64 h60
  text "TOLERANCE:" at 11404.23,4573.64 h60
  text "X" at 12243.53,4573.64 h60
  text "ANSI IPC-6012 TYPE 3 CLASS 2" at 12430.48,4573.64 h60
  text "OTHER +/-" at 12430.46,4417.64 h60
  text "BOW & TWIST:" at 11404.23,4260.64 h60
  text "X" at 12243.53,4260.64 h60
  text "ANSI IPC-6012 TYPE 3 CLASS 2" at 12430.48,4260.64 h60
  text "OTHER +/-" at 12430.46,4102.13 h60
  text "DRILLING:" at 11329.46,3963.64 h60
  text "REFERENCE:" at 11404.23,3846.64 h60
  text "X" at 12052.46,3846.64 h60
  text "AS SHOWN" at 12239.46,3846.64 h60
  text "X" at 12953.46,3846.64 h60
  text "NC_DRILL FILES" at 13090.46,3846.64 h60
  text "PTH COPPER THICKNESS:" at 11404.23,3688.64 h60
  text "X" at 12534.46,3688.64 h60
  text "20-30 um" at 12671.46,3688.64 h60
  text "OTHER" at 13388.46,3688.64 h60
  text "BOARD FINISH:" at 11329.46,3529.64 h60
  text "SILKSCREEN:" at 11484.68,3411.64 h60
  text "X" at 12433.46,3411.64 h60
  text "TOP" at 12559.46,3411.64 h60
  text "X" at 12943.46,3411.64 h60
  text "BOTTOM" at 13070.46,3411.64 h60
  text "SILKSCREEN COLOR:" at 11484.68,3244.64 h60
  text "X" at 12432.42,3244.64 h60
  text "WHITE" at 12559.46,3244.64 h60
  text "OTHER" at 13070.46,3244.64 h60
  text "X" at 12563.42,3085.44 h60
  text "GREEN" at 12690.46,3085.44 h60
  text "OTHER" at 13308.46,3085.44 h60
  text "SOLDER RESIST COLOR:" at 11484.68,3074.64 h60
  text "X" at 12563.42,2915.44 h60
  text "MATTE" at 12690.46,2915.44 h60
  text "SEMI-GLOSS" at 13308,2914.8 h60
  text "IMMERSION GOLD (ENIG)" at 12390.46,2726.92 h60
  text "ENEPIG" at 13728,2723.64 h60
  text "SURFACE FINISH:" at 11329.46,2722.64 h60
  text "X" at 12203.51,2722.64 h60
  text "IMM. TIN/SILVER OR EQUIV" at 11659,2565.64 h60
  text "OTHER" at 13090.46,2565.64 h60
  text "ARRAY/PANEL:" at 11329.46,2386.64 h60
  text "CUT AND TRIM PER M1 BOARD OUTLINE" at 12390.46,2382.35 h60
  text "N.C. ROUTE" at 12390.46,2230.64 h60
  text "X" at 13069.46,2230.64 h60
  text "V. SCORE" at 13256.46,2230.64 h60
  text "CERTIFICATION:" at 11329.46,2093.64 h60
  text "MATERIALS AND WORKMANSHIP FOR ALL PCBS" at 12054.46,2093.64 h60
  text "TO MEET OR EXCEED THE REQUIREMENTS OF:" at 12054.46,1995.64 h60
  text "X" at 11680.96,1859.13 h60
  text "ANSI IPC-A-600F CLASS ->" at 11819.96,1859.13 h60
  text "X" at 13459.02,1859.13 h60
  text "2" at 13577.96,1859.14 h60
  text "1" at 13262.96,1857.64 h60
  text "3" at 13931.96,1857.64 h60
  text "X" at 12495.02,1699.64 h60
  text "RoHS" at 12631.96,1699.64 h60
  text "OTHER" at 13276.36,1699.64 h60
  text "PER ORDER" at 13673.42,1699.64 h60
  text "ALL BOARDS MUST MEET OR EXCEED UL94-V0 REQUIREMENTS." at 11357,1534 h60
  text "PCB MUST BEAR THE UL94V-0 UL REGISTERED MATERIAL ID NUMBER" at 11357,1414 h60
  text "ADDITIONAL REQUIREMENTS:" at 11329.46,1240.64 h60
  text "MICROSECTION:" at 11404.23,1125.64 h60
  text "YES" at 12309.96,1125.64 h60
  text "REQUIRED" at 13171.46,969.49 h60
  text "BARE BOARD ELEC. TEST:" at 11404.23,966.64 h60
  text "NONE" at 12709.96,966.64 h60
  text "X" at 13044.46,966.64 h60
  text "PER ORDER" at 13763.46,966.64 h60
  text ".Layer_Name" at 577,-858.49 h60
M11 Gerber Information:
  lines w10: -292,-930.17 6308,-930.17 ; -292,-726.83 6310,-726.83 ; -292,-523.5 -292,-1133.5 3713,-1133.5 6310,-1133.5 6310,-523.5 -291.5,-523.5 -291.5,-1133.5 1284,-1133.5 ; 2173,-1133.5 2173,-523.5 ; 3440,-726.83 3440,-523.5 ; 4280,-726.83 4280,-523.5 ; 4902,-1140 4902,-937.17
  text "ALL ARTWORK VIEWED FROM TOP SIDE" at -228.5,-655.67 h60
  text "BOARD #:" at 2248,-655.67 h60
  text ".PRJ_Number" at 2793.5,-655.67 h60
  text "REV:" at 3638,-655.67 h60
  text ".PCB_Rev" at 3929.5,-655.67 h60
  text "SVN REV:" at 4476,-655.67 h60
  text ".VersionControl_RevNumber" at 4982,-655.67 h60
  text "LAYER NAME =" at -228.5,-858.49 h60
  text "TID #:" at 2248,-859 h60
  text ".TID" at 2793.5,-859 h60
  text "PLOT NAME =" at -228.5,-1064.34 h60
  text ".plot_File_Name" at 577,-1064.34 h60
  text "GENERATED    :" at 2250,-1064.34 h60
  text ".Print_Date" at 3119.5,-1064.34 h60
  text ".Print_Time" at 3848.5,-1064.34 h60
  text "TEXAS INSTRUMENTS" at 5113,-1064.34 h60
M12 Stackup:
  drawing of 191 lines, arcs and shapes, not listed
  text "Layer" at 9790.34,7830 h60
  text "Name" at 10200.26,7830 h60
  text "Material" at 11130,7830 h60
  text "Thickness" at 11989.77,7830 h60
  text "Constant" at 12639.6,7830 h60
  text "Board Layer Stack" at 13209.46,7830 h60
  text "1" at 9790.34,7710 h60
  text "Top Overlay" at 10200.26,7710 h60
  text "2" at 9790.34,7590 h60
  text "Top Solder" at 10200.26,7590 h60
  text "Solder Resist" at 11130,7590 h60
  text "0.40mil" at 11989.77,7590 h60
  text "3.5" at 12639.6,7590 h60
  text "3" at 9790.34,7470 h60
  text "Top Layer" at 10200.26,7470 h60
  text "Copper" at 11130,7470 h60
  text "1.40mil" at 11989.77,7470 h60
  text "4" at 9790.34,7350 h60
  text "Dielectric1" at 10200.26,7350 h60
  text "FR-4" at 11130,7350 h60
  text "59.20mil" at 11989.77,7350 h60
  text "4.8" at 12639.6,7350 h60
  text "5" at 9790.34,7230 h60
  text "Bottom Layer" at 10200.26,7230 h60
  text "Copper" at 11130,7230 h60
  text "1.40mil" at 11989.77,7230 h60
  text "6" at 9790.34,7110 h60
  text "Bottom Solder" at 10200.26,7110 h60
  text "Solder Resist" at 11130,7110 h60
  text "0.40mil" at 11989.77,7110 h60
  text "3.5" at 12639.6,7110 h60
  text "7" at 9790.34,6990 h60
  text "Bottom Overlay" at 10200.26,6990 h60
  text ".Layer_Name" at 577,-858.49 h60
M13 Component Bodies Top:
  text ".Layer_Name" at 577,-858.49 h60
M14 Component Bodies Bottom:
  text ".Layer_Name" at 577,-858.49 h60
M15 Courtyards Top:
  text ".Layer_Name" at 577,-858.49 h60
M16 Courtyards Bottom:
  text ".Layer_Name" at 577,-858.49 h60
Drill Drawing:
  circle w10: c5363.72,3017.64 r16.58
  circle w10: c5363.72,3017.64 r27.63
  circle w10: c5363.72,2147.4 r27.63
  lines w10: 5336.09,2244.1 5391.34,2244.1 5391.34,2299.35 5336.09,2299.35 5336.09,2244.1 ; 5336.09,2423.67 5391.34,2423.67 5363.72,2368.42 5336.09,2423.67 ; 5336.09,2492.74 5363.72,2506.55 5391.34,2492.74 5377.53,2520.36 5391.34,2547.99 5363.72,2534.18 5336.09,2547.99 5349.9,2520.36 5336.09,2492.74 ; 5336.09,2630.87 5349.9,2630.87 5349.9,2617.06 5377.53,2617.06 5377.53,2630.87 5391.34,2630.87 5391.34,2658.5 5377.53,2658.5 5377.53,2672.31 5349.9,2672.31 5349.9,2658.5 5336.09,2658.5 5336.09,2630.87 ; 5336.09,2769 5363.72,2741.38 5391.34,2769 5363.72,2796.63 5336.09,2769 ; 5336.09,2865.7 5336.09,2879.51 5349.9,2893.32 5336.09,2907.14 5336.09,2920.95 5349.9,2920.95 5363.72,2907.14 5377.53,2920.95 5391.34,2920.95 5391.34,2907.14 5377.53,2893.32 5391.34,2879.51 5391.34,2865.7 5377.53,2865.7 5363.72,2879.51 5349.9,2865.7 5336.09,2865.7 ; 5336.09,3169.59 5391.34,3169.59 5363.72,3114.34 5336.09,3169.59 ; 5336.09,3238.66 5391.34,3238.66 5391.34,3293.91 5336.09,3293.91 5336.09,3238.66 ; 5347.14,2412.62 5380.29,2412.62 5363.72,2379.47 5347.14,2412.62 ; 5347.14,3249.71 5380.29,3249.71 5380.29,3282.86 5347.14,3282.86 5347.14,3249.71
  lines w12: 5286,2082.48 8517.49,2082.48 ; 5286,3325.68 8517.49,3325.68 ; 5623.86,1958.16 5623.86,3450 ; 5955.86,1958.16 5955.86,3450 ; 6592.43,1958.16 6592.43,3450 ; 6851.57,1958.16 6851.57,3450 ; 7226.72,1958.16 7226.72,3450 ; 7951.05,1958.16 7951.05,3450 ; 5286,1958.16 8517.49,1958.16 8517.49,3450 5286,3450 5286,1958.16
  text "Symbol" at 5360.59,3362.98 h72
  text "Quantity" at 5661.16,3362.98 h72
  text "Finished Hole Size" at 5993.16,3362.98 h72
  text "Plated" at 6629.72,3362.98 h72
  text "Hole Type" at 6888.86,3362.98 h72
  text "Drill Layer Pair" at 7264.02,3362.98 h72
  text "Hole Tolerance" at 7988.35,3362.98 h72
  text "12" at 5661.16,3238.66 h60
  text "7.87mil (0.200mm)" at 5993.16,3238.66 h60
  text "PTH" at 6629.72,3238.66 h60
  text "Round" at 6888.86,3238.66 h60
  text "Top Layer - Bottom Layer" at 7264.02,3238.66 h60
  text "62" at 5661.16,3114.34 h60
  text "16.00mil (0.406mm)" at 5993.16,3114.34 h60
  text "PTH" at 6629.72,3114.34 h60
  text "Round" at 6888.86,3114.34 h60
  text "Top Layer - Bottom Layer" at 7264.02,3114.34 h60
  text "4" at 5661.16,2990.02 h60
  text "33.46mil (0.850mm)" at 5993.16,2990.02 h60
  text "PTH" at 6629.72,2990.02 h60
  text "Round" at 6888.86,2990.02 h60
  text "Top Layer - Bottom Layer" at 7264.02,2990.02 h60
  text "2" at 5661.16,2865.7 h60
  text "39.37mil (1.000mm)" at 5993.16,2865.7 h60
  text "PTH" at 6629.72,2865.7 h60
  text "Round" at 6888.86,2865.7 h60
  text "Top Layer - Bottom Layer" at 7264.02,2865.7 h60
  text "8" at 5661.16,2741.38 h60
  text "40.00mil (1.016mm)" at 5993.16,2741.38 h60
  text "PTH" at 6629.72,2741.38 h60
  text "Round" at 6888.86,2741.38 h60
  text "Top Layer - Bottom Layer" at 7264.02,2741.38 h60
  text "2" at 5661.16,2617.06 h60
  text "41.34mil (1.050mm)" at 5993.16,2617.06 h60
  text "PTH" at 6629.72,2617.06 h60
  text "Round" at 6888.86,2617.06 h60
  text "Top Layer - Bottom Layer" at 7264.02,2617.06 h60
  text "2" at 5661.16,2492.74 h60
  text "45.28mil (1.150mm)" at 5993.16,2492.74 h60
  text "PTH" at 6629.72,2492.74 h60
  text "Round" at 6888.86,2492.74 h60
  text "Top Layer - Bottom Layer" at 7264.02,2492.74 h60
  text "3" at 5661.16,2368.42 h60
  text "52.00mil (1.321mm)" at 5993.16,2368.42 h60
  text "PTH" at 6629.72,2368.42 h60
  text "Round" at 6888.86,2368.42 h60
  text "Top Layer - Bottom Layer" at 7264.02,2368.42 h60
  text "6" at 5661.16,2244.1 h60
  text "57.00mil (1.448mm)" at 5993.16,2244.1 h60
  text "PTH" at 6629.72,2244.1 h60
  text "Round" at 6888.86,2244.1 h60
  text "Top Layer - Bottom Layer" at 7264.02,2244.1 h60
  text "4" at 5661.16,2119.78 h60
  text "125.98mil (3.200mm)" at 5993.16,2119.78 h60
  text "PTH" at 6629.72,2119.78 h60
  text "Round" at 6888.86,2119.78 h60
  text "Top Layer - Bottom Layer" at 7264.02,2119.78 h60
  text "105 Total" at 5661.16,1995.46 h60
  text ".Layer_Name" at 577,-858.49 h60
M17 Embedded Cavity:
  text ".Layer_Name" at 577,-858.49 h60
M18 Embedded Assembly:
  text ".Layer_Name" at 577,-858.49 h60
M19 Embedded Keepout:
  text ".Layer_Name" at 577,-858.49 h60

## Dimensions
0,0 to 4950,0 on M2 Board Dimensions
0,0 to 0,3450 on M2 Board Dimensions
0,-400 to 1000,-400 on M2 Board Dimensions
